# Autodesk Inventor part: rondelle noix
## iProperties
Author: Administrateur
Created: 2001-04
Part Number: rondelle noix
Material: Par défaut
Document SubType Name: Modélisation
Designer: Administrateur
Control State: 0
Master: False
Checked Out: False
PropertySet Name: Design Tracking Control
Shininess: 20.0
PropertySet Name: _Private Model Information
Length Units: 11269
Angle Units: 11283
Time Units: 11279
Mass Units: 11290
Length Display Precision: 3
Angle Display Precision: 2
Compacted: False
Density: 0.0
Volumn: 0.0
Area: 0.0
PropertySet Name: Model Information
